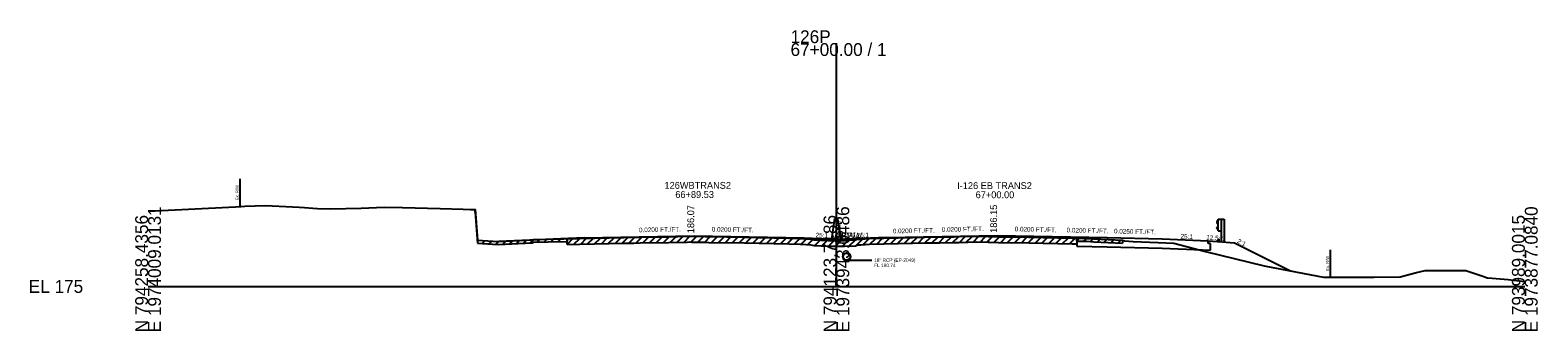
# Model space of a CAD drawing. Extents: x -161 to 1970889, y -4362 to 797231.
# Drawn here: x 2974.3 to 3302.8, y 1990.3 to 2056 of the extents above; entities that cross this region are included whole.
import ezdxf

# ---------------------------------------------------------------- set-up
doc = ezdxf.new("R2010")
doc.units = 0
for name, color, linetype in [('Default', 7, 'Continuous'), ('RD_GPK_XS_Cell', 7, 'Continuous'), ('RD_XS_Base', 7, 'Continuous'), ('RD_XS_CurbTop', 7, 'Continuous'), ('RD_XS_EarthShd', 7, 'Continuous'), ('RD_XS_ExGround', 7, 'Continuous'), ('RD_XS_ExPaveRet', 7, 'Continuous'), ('RD_XS_ExRW', 7, 'Continuous'), ('RD_XS_GR', 7, 'Continuous'), ('RD_XS_MedBWall', 7, 'Continuous'), ('RD_XS_Misc_Line', 7, 'Continuous'), ('RD_XS_Pave', 7, 'Continuous'), ('RD_XS_PaveOvlay', 7, 'Continuous'), ('RD_XS_PaveShd', 7, 'Continuous'), ('RD_XS_Pipe', 7, 'Continuous'), ('RD_XS_TieSlope', 7, 'Continuous'), ('RD_XS_TX_Elev_EX', 7, 'Continuous'), ('RD_XS_TX_Elev_PR', 7, 'Continuous'), ('RD_XS_TX_MkPT', 7, 'Continuous'), ('RD_XS_TX_Profile', 7, 'Continuous'), ('RD_XS_TX_ShdSlope', 7, 'Continuous'), ('RD_XS_TX_Slope', 7, 'Continuous'), ('RD_XS_TX_Station', 7, 'Continuous')]:
    doc.layers.add(name, color=color, linetype=linetype)

msp = doc.modelspace()

# ---------------------------------------------------------------- linework, layer by layer
at = {"layer": 'RD_GPK_XS_Cell'}
for p, q in [((3150, 2000), (3150, 2053.11)), ((3000, 2000), (3150, 2000)), ((3150, 2000), (3300, 2000))]:
    msp.add_line(p, q, dxfattribs=at)
at = {"layer": 'RD_XS_Base'}
for p, q in [((3202.36, 2008.77), (3209, 2008.63)), ((3209, 2008.63), (3221, 2008.33)), ((3221, 2008.33), (3231.51, 2007.91)), ((3231.01, 2009.41), (3231.01, 2009.97)), ((3231.51, 2009.39), (3231.01, 2009.41)), ((3231.51, 2007.91), (3231.51, 2009.39))]:
    msp.add_line(p, q, dxfattribs=at)
at = {"layer": 'RD_XS_CurbTop'}
for p, q in [((3233.01, 2009.81), (3233.26, 2010.27)), ((3233.01, 2009.81), (3233.48, 2009.78)), ((3233.48, 2009.78), (3233.42, 2010.21))]:
    msp.add_line(p, q, dxfattribs=at)
msp.add_ellipse((3233.33, 2010.19), major_axis=(0, -0.131), ratio=0.686, start_param=1.762783, end_param=4.036677, dxfattribs=at)
at = {"layer": 'RD_XS_EarthShd'}
msp.add_line((3231.01, 2009.97), (3233.01, 2009.81), dxfattribs=at)
at = {"layer": 'RD_XS_ExGround'}
msp.add_lwpolyline([(3000, 2016.45), (3019.02, 2017.4), (3020.26, 2017.48), (3021.08, 2017.51), (3025.56, 2017.7), (3031.48, 2017.39), (3032.92, 2017.33), (3034.11, 2017.23), (3035.91, 2017.07), (3036.91, 2017.04), (3039.67, 2016.92), (3046.47, 2017.09), (3051.43, 2017.29), (3055.44, 2017.25), (3063.66, 2017.02), (3068.69, 2016.88), (3070.27, 2016.83), (3071.29, 2016.83), (3071.82, 2010.08), (3075.16, 2009.89), (3076.45, 2009.81), (3080.66, 2010.02), (3083.72, 2010.16), (3083.97, 2010.27), (3087.2, 2010.35), (3094.07, 2010.49), (3103.67, 2010.69), (3105.88, 2010.73), (3107.23, 2010.75), (3113.42, 2010.86), (3117.49, 2010.95), (3118.06, 2010.96), (3118.49, 2010.95), (3121.37, 2010.89), (3122.23, 2010.88), (3129.88, 2010.77), (3139.63, 2010.54), (3142.11, 2010.48), (3142.43, 2010.46), (3144.43, 2010.36), (3145.04, 2010.2), (3148.19, 2010.04), (3150, 2010.03), (3150.51, 2010.03), (3151.1, 2010.03), (3151.75, 2010.05), (3154.17, 2010.15), (3154.67, 2010.33), (3155.3, 2010.36), (3157.17, 2010.45), (3166.57, 2010.68), (3169.25, 2010.75), (3172.52, 2010.8), (3175.62, 2010.85), (3176.72, 2010.88), (3180.53, 2010.96), (3183.03, 2010.9), (3183.46, 2010.89), (3185.28, 2010.86), (3191.93, 2010.76), (3201.37, 2010.55), (3204.54, 2010.48), (3206.07, 2010.41), (3212.36, 2010.09), (3212.78, 2009.98), (3214.64, 2009.82), (3220.08, 2009.59), (3223.54, 2009.44), (3230.4, 2007.65), (3243.21, 2004.53), (3253.43, 2002.57), (3256.12, 2002.02), (3261.58, 2002.03), (3266.6, 2002.03), (3267.17, 2002.04), (3272.84, 2002.13), (3276.41, 2003.03), (3278.27, 2003.52), (3280.62, 2003.52), (3287.12, 2003.52), (3290.44, 2002.38), (3291.89, 2001.89), (3292.85, 2001.81), (3296.35, 2001.5), (3300, 2001.1)], dxfattribs=at)
at = {"layer": 'RD_XS_ExPaveRet'}
for p, q in [((3071.29, 2016.2), (3071.29, 2016.83)), ((3071.29, 2016.2), (3071.82, 2009.45)), ((3071.82, 2009.45), (3075.16, 2009.27)), ((3075.16, 2009.27), (3076.45, 2009.18)), ((3076.45, 2009.18), (3080.66, 2009.39)), ((3080.66, 2009.39), (3083.72, 2009.54)), ((3083.72, 2009.54), (3083.97, 2009.65)), ((3083.97, 2009.65), (3087.2, 2009.72)), ((3087.2, 2009.72), (3091.29, 2009.81)), ((3091.29, 2009.18), (3091.29, 2010.43)), ((3091.29, 2010.43), (3091.29, 2009.81)), ((3091.29, 2009.18), (3094.07, 2009.24)), ((3094.07, 2009.24), (3103.67, 2009.44)), ((3103.67, 2009.44), (3105.88, 2009.48)), ((3105.88, 2009.48), (3107.23, 2009.5)), ((3107.23, 2009.5), (3113.42, 2009.61)), ((3113.42, 2009.61), (3117.49, 2009.7)), ((3117.49, 2009.7), (3118.06, 2009.71)), ((3118.06, 2009.71), (3118.49, 2009.7)), ((3118.49, 2009.7), (3121.37, 2009.64)), ((3121.37, 2009.64), (3122.23, 2009.63)), ((3122.23, 2009.63), (3129.88, 2009.52)), ((3129.88, 2009.52), (3139.63, 2009.29)), ((3139.63, 2009.29), (3142.11, 2009.23)), ((3142.11, 2009.23), (3142.43, 2009.21)), ((3142.43, 2009.21), (3144.43, 2009.11)), ((3144.43, 2009.11), (3145.04, 2008.95)), ((3145.04, 2008.95), (3148.19, 2008.79)), ((3148.19, 2008.79), (3150, 2008.78)), ((3150, 2008.78), (3150.51, 2008.78)), ((3150.51, 2008.78), (3151.1, 2008.78)), ((3151.1, 2008.78), (3151.75, 2008.8)), ((3151.75, 2008.8), (3154.17, 2008.9)), ((3154.17, 2008.9), (3154.67, 2009.08)), ((3154.67, 2009.08), (3155.3, 2009.11)), ((3155.3, 2009.11), (3157.17, 2009.2)), ((3157.17, 2009.2), (3166.57, 2009.43)), ((3166.57, 2009.43), (3169.25, 2009.5)), ((3169.25, 2009.5), (3172.52, 2009.55)), ((3172.52, 2009.55), (3175.62, 2009.6)), ((3175.62, 2009.6), (3176.72, 2009.63)), ((3176.72, 2009.63), (3180.53, 2009.71)), ((3180.53, 2009.71), (3183.03, 2009.65)), ((3183.03, 2009.65), (3183.46, 2009.64)), ((3183.46, 2009.64), (3185.28, 2009.61)), ((3185.28, 2009.61), (3191.93, 2009.51)), ((3191.93, 2009.51), (3201.37, 2009.3)), ((3201.37, 2009.3), (3202.36, 2009.28)), ((3202.36, 2010.53), (3202.36, 2009.28)), ((3202.36, 2009.91), (3202.36, 2010.53)), ((3202.36, 2009.91), (3204.54, 2009.86)), ((3204.54, 2009.86), (3206.07, 2009.78)), ((3206.07, 2009.78), (3212.36, 2009.46)), ((3212.36, 2010.09), (3212.36, 2009.46))]:
    msp.add_line(p, q, dxfattribs=at)
at = {"layer": 'RD_XS_ExRW'}
for p, q in [((3020, 2023.46), (3020, 2017.46)), ((3257.55, 2008.02), (3257.55, 2002.02))]:
    msp.add_line(p, q, dxfattribs=at)
at = {"layer": 'RD_XS_GR'}
for p, q in [((3233.16, 2014.53), (3232.89, 2014.09)), ((3232.89, 2014.09), (3232.89, 2013.98)), ((3232.89, 2013.98), (3233.16, 2013.54)), ((3233.16, 2014.69), (3233.82, 2014.69)), ((3233.16, 2012.12), (3233.16, 2014.69)), ((3233.82, 2014.69), (3234.49, 2014.69)), ((3233.82, 2014.69), (3233.82, 2009.75)), ((3234.49, 2014.69), (3234.49, 2009.64)), ((3232.89, 2012.83), (3233.16, 2013.27)), ((3232.89, 2012.72), (3232.89, 2012.83)), ((3233.16, 2012.28), (3232.89, 2012.72)), ((3233.16, 2012.12), (3233.82, 2012.12))]:
    msp.add_line(p, q, dxfattribs=at)
at = {"layer": 'RD_XS_MedBWall'}
for p, q in [((3149, 2010.33), (3149.67, 2014.81)), ((3150.33, 2014.81), (3149.67, 2014.81)), ((3150.33, 2014.73), (3150.33, 2014.81)), ((3151, 2010.25), (3150.33, 2014.73))]:
    msp.add_line(p, q, dxfattribs=at)
at = {"layer": 'RD_XS_Misc_Line'}
for p, q in [((3071.29, 2016.2), (3071.33, 2016.25)), ((3100.29, 2009.37), (3101.56, 2010.64)), ((3101.79, 2009.4), (3103.06, 2010.67)), ((3103.29, 2009.43), (3104.56, 2010.7)), ((3104.79, 2009.46), (3106.06, 2010.73)), ((3106.29, 2009.48), (3107.56, 2010.76)), ((3107.79, 2009.51), (3109.06, 2010.79)), ((3109.29, 2009.54), (3110.56, 2010.81)), ((3110.79, 2009.57), (3112.06, 2010.84)), ((3112.29, 2009.59), (3113.56, 2010.86)), ((3113.79, 2009.62), (3115.06, 2010.9)), ((3115.29, 2009.65), (3116.56, 2010.93)), ((3116.79, 2009.68), (3118.06, 2010.96)), ((3118.29, 2009.7), (3119.51, 2010.93)), ((3119.79, 2009.67), (3121.02, 2010.9)), ((3121.29, 2009.65), (3122.52, 2010.88)), ((3122.79, 2009.62), (3124.02, 2010.85)), ((3124.29, 2009.6), (3125.52, 2010.83)), ((3125.79, 2009.58), (3127.02, 2010.81)), ((3127.29, 2009.56), (3128.52, 2010.79)), ((3128.79, 2009.53), (3130.02, 2010.76)), ((3130.29, 2009.51), (3131.51, 2010.73)), ((3131.79, 2009.47), (3133.01, 2010.69)), ((3133.29, 2009.44), (3134.51, 2010.66)), ((3134.79, 2009.4), (3136.01, 2010.62)), ((3163.29, 2009.35), (3164.57, 2010.63)), ((3164.79, 2009.38), (3166.07, 2010.67)), ((3166.29, 2009.42), (3167.57, 2010.71)), ((3167.79, 2009.46), (3169.07, 2010.75)), ((3169.29, 2009.5), (3170.56, 2010.77)), ((3170.79, 2009.52), (3172.06, 2010.79)), ((3172.29, 2009.54), (3173.56, 2010.81)), ((3173.79, 2009.57), (3175.06, 2010.84)), ((3175.29, 2009.6), (3176.57, 2010.87)), ((3176.79, 2009.63), (3178.07, 2010.91)), ((3178.29, 2009.66), (3179.57, 2010.94)), ((3179.79, 2009.7), (3181.04, 2010.95)), ((3181.29, 2009.7), (3182.51, 2010.92)), ((3182.79, 2009.66), (3184.01, 2010.88)), ((3184.29, 2009.63), (3185.52, 2010.86)), ((3185.79, 2009.61), (3187.02, 2010.84)), ((3187.29, 2009.58), (3188.52, 2010.81)), ((3188.79, 2009.56), (3190.02, 2010.79)), ((3190.29, 2009.53), (3191.52, 2010.76)), ((3191.79, 2009.51), (3193.01, 2010.73)), ((3193.29, 2009.48), (3194.51, 2010.7)), ((3194.79, 2009.44), (3196.01, 2010.67)), ((3196.29, 2009.41), (3197.51, 2010.64)), ((3072.79, 2009.4), (3073.38, 2009.99)), ((3074.29, 2009.31), (3074.88, 2009.91)), ((3075.79, 2009.22), (3076.37, 2009.81)), ((3077.29, 2009.22), (3077.95, 2009.88)), ((3078.79, 2009.3), (3079.45, 2009.96)), ((3080.29, 2009.38), (3080.95, 2010.03)), ((3081.79, 2009.45), (3082.44, 2010.1)), ((3083.29, 2009.52), (3084.04, 2010.27)), ((3084.79, 2009.67), (3085.43, 2010.31)), ((3086.29, 2009.7), (3086.93, 2010.34)), ((3087.79, 2009.73), (3088.43, 2010.37)), ((3089.29, 2009.77), (3089.93, 2010.4)), ((3091.29, 2009.18), (3092.57, 2010.46)), ((3092.79, 2009.22), (3094.07, 2010.49)), ((3094.29, 2009.25), (3095.56, 2010.52)), ((3095.79, 2009.28), (3097.06, 2010.55)), ((3097.29, 2009.31), (3098.56, 2010.58)), ((3098.79, 2009.34), (3100.06, 2010.61)), ((3136.29, 2009.37), (3137.51, 2010.59)), ((3137.79, 2009.33), (3139.01, 2010.55)), ((3139.29, 2009.29), (3140.51, 2010.52)), ((3140.79, 2009.26), (3142.01, 2010.48)), ((3142.29, 2009.22), (3143.48, 2010.41)), ((3143.79, 2009.14), (3144.89, 2010.24)), ((3145.29, 2008.94), (3146.48, 2010.13)), ((3146.79, 2008.86), (3147.98, 2010.05)), ((3148.29, 2008.79), (3149.53, 2010.03)), ((3149.79, 2008.78), (3151.04, 2010.03)), ((3151.29, 2008.79), (3152.59, 2010.08)), ((3152.79, 2008.84), (3154.09, 2010.14)), ((3154.29, 2008.94), (3155.73, 2010.38)), ((3155.79, 2009.13), (3157.1, 2010.44)), ((3157.29, 2009.2), (3158.57, 2010.48)), ((3158.79, 2009.24), (3160.07, 2010.52)), ((3160.29, 2009.27), (3161.57, 2010.56)), ((3161.79, 2009.31), (3163.07, 2010.59)), ((3197.79, 2009.38), (3199.01, 2010.6)), ((3199.29, 2009.35), (3200.51, 2010.57)), ((3200.79, 2009.32), (3202.01, 2010.54)), ((3202.36, 2009.91), (3202.97, 2010.52)), ((3203.86, 2009.87), (3204.47, 2010.49)), ((3205.36, 2009.82), (3205.95, 2010.42)), ((3206.86, 2009.74), (3207.45, 2010.34)), ((3208.36, 2009.67), (3208.95, 2010.26)), ((3209.86, 2009.59), (3210.45, 2010.18)), ((3211.36, 2009.51), (3211.95, 2010.11))]:
    msp.add_line(p, q, dxfattribs=at)
at = {"layer": 'RD_XS_Pave'}
for p, q in [((3095, 2010.59), (3119, 2011.07)), ((3119, 2011.07), (3143, 2010.59)), ((3161, 2010.67), (3185, 2011.15)), ((3185, 2011.15), (3209, 2010.67)), ((3209, 2010.67), (3221, 2010.37))]:
    msp.add_line(p, q, dxfattribs=at)
at = {"layer": 'RD_XS_PaveOvlay'}
for p, q in [((3157.17, 2010.45), (3166.57, 2010.68)), ((3166.57, 2010.68), (3169.25, 2010.75)), ((3169.25, 2010.75), (3172.52, 2010.8)), ((3172.52, 2010.8), (3175.62, 2010.85)), ((3175.62, 2010.85), (3176.72, 2010.88)), ((3176.72, 2010.88), (3180.53, 2010.96)), ((3180.53, 2010.96), (3183.03, 2010.9)), ((3183.03, 2010.9), (3183.46, 2010.89)), ((3183.46, 2010.89), (3185.28, 2010.86)), ((3185.28, 2010.86), (3191.93, 2010.76)), ((3191.93, 2010.76), (3201.37, 2010.55)), ((3150, 2010.03), (3150.51, 2010.03)), ((3150.51, 2010.03), (3151.1, 2010.03)), ((3151.1, 2010.03), (3151.75, 2010.05)), ((3151.75, 2010.05), (3154.17, 2010.15)), ((3154.17, 2010.15), (3154.67, 2010.33)), ((3154.67, 2010.33), (3155.3, 2010.36)), ((3155.3, 2010.36), (3157.17, 2010.45)), ((3201.37, 2010.55), (3202.36, 2010.53)), ((3202.36, 2010.53), (3202.36, 2008.77))]:
    msp.add_line(p, q, dxfattribs=at)
at = {"layer": 'RD_XS_PaveShd'}
for p, q in [((3161, 2010.67), (3150, 2010.23)), ((3095, 2010.59), (3076.45, 2009.81)), ((3143, 2010.59), (3150, 2010.31)), ((3221, 2010.37), (3231.01, 2009.97))]:
    msp.add_line(p, q, dxfattribs=at)
at = {"layer": 'RD_XS_Pipe'}
msp.add_line((3152.72, 2005.74), (3157.72, 2005.74), dxfattribs=at)
for radius in [0.85, 0.75]:
    msp.add_circle((3152.22, 2006.49), radius, dxfattribs=at)
at = {"layer": 'RD_XS_TieSlope'}
for p, q in [((3233.01, 2009.81), (3236.76, 2009.52)), ((3236.76, 2009.52), (3248.95, 2003.43))]:
    msp.add_line(p, q, dxfattribs=at)

# ---------------------------------------------------------------- texts
at = {"layer": 'Default'}
for p in [(3150, 2010.31), (3150, 2010.2)]:
    msp.add_text('35', height=1.5, dxfattribs=at).set_placement(p)
at = {"layer": 'RD_GPK_XS_Cell'}
for s, p in [('126P', (3140, 2053.11)), ('67+00.00 / 1', (3140, 2050.31)), ('EL 175', (2974, 1998.6))]:
    msp.add_text(s, height=2.8, dxfattribs=at).set_placement(p)
for s, p in [('E 1974009.0131', (3002.8, 1990)), ('E 1973943.0486', (3152.8, 1990)), ('E 1973877.0840', (3302.8, 1990)), ('N 794258.4356', (3000, 1990)), ('N 794123.7186', (3150, 1990)), ('N 793989.0015', (3300, 1990))]:
    msp.add_text(s, height=2.8, rotation=90, dxfattribs=at).set_placement(p)
at = {"layer": 'RD_XS_ExRW'}
for p in [(3019.75, 2018.85), (3257.3, 2003.4)]:
    msp.add_text('Ex. R/W ', height=0.65, rotation=90, dxfattribs=at).set_placement(p)
at = {"layer": 'RD_XS_Pipe'}
for s, p in [('18" RCP (EP-2049)', (3158.22, 2005.37)), ('FL 180.74', (3158.22, 2004.24))]:
    msp.add_text(s, height=0.75, dxfattribs=at).set_placement(p)
at = {"layer": 'RD_XS_TX_Elev_EX'}
msp.add_text('185.03', height=1, rotation=90, dxfattribs=at).set_placement((3151, 2010.03))
at = {"layer": 'RD_XS_TX_Elev_PR'}
for s, p in [(' 186.07', (3119, 2011.07)), (' 186.15', (3185, 2011.15))]:
    msp.add_text(s, height=1.5, rotation=90, dxfattribs=at).set_placement(p)
at = {"layer": 'RD_XS_TX_MkPT'}
for s, p in [('WBW', (3149, 2010.33)), ('EBW', (3151, 2010.25))]:
    msp.add_text(s, height=1.5, dxfattribs=at).set_placement(p)
at = {"layer": 'RD_XS_TX_Profile'}
for rotation, p in [(357.7094, (3145.46, 2010.74)), (2.2906, (3154.44, 2010.66)), (357.7112, (3224.96, 2010.47))]:
    msp.add_text('25:1', height=1, rotation=rotation, dxfattribs=at).set_placement(p)
at = {"layer": 'RD_XS_TX_ShdSlope'}
msp.add_text('12.5:1', height=1, rotation=355.4297, dxfattribs=at).set_placement((3230.55, 2010.26))
at = {"layer": 'RD_XS_TX_Slope'}
for s, rotation, p in [('0.0200 FT./FT.', 1.1458, (3106.98, 2011.83)), ('0.0200 FT./FT.', 358.8542, (3122.83, 2011.99)), ('0.0200 FT./FT.', 1.1458, (3162.3, 2011.59)), ('0.0200 FT./FT.', 1.1458, (3172.98, 2011.91)), ('0.0200 FT./FT.', 358.569, (3188.84, 2012.06)), ('0.0200 FT./FT.', 358.5681, (3200.15, 2011.83)), ('0.0250 FT./FT.', 358.569, (3210.47, 2011.6)), ('2:1', 333.4349, (3237.23, 2009.58))]:
    msp.add_text(s, height=1, rotation=rotation, dxfattribs=at).set_placement(p)
at = {"layer": 'RD_XS_TX_Station'}
for s, p in [('126WBTRANS2', (3112.53, 2021.32)), ('66+89.53', (3114.89, 2019.32)), ('I-126 EB TRANS2', (3176.31, 2021.26)), ('67+00.00', (3180.33, 2019.26))]:
    msp.add_text(s, height=1.5, dxfattribs=at).set_placement(p)

doc.saveas('drawing.dxf')
